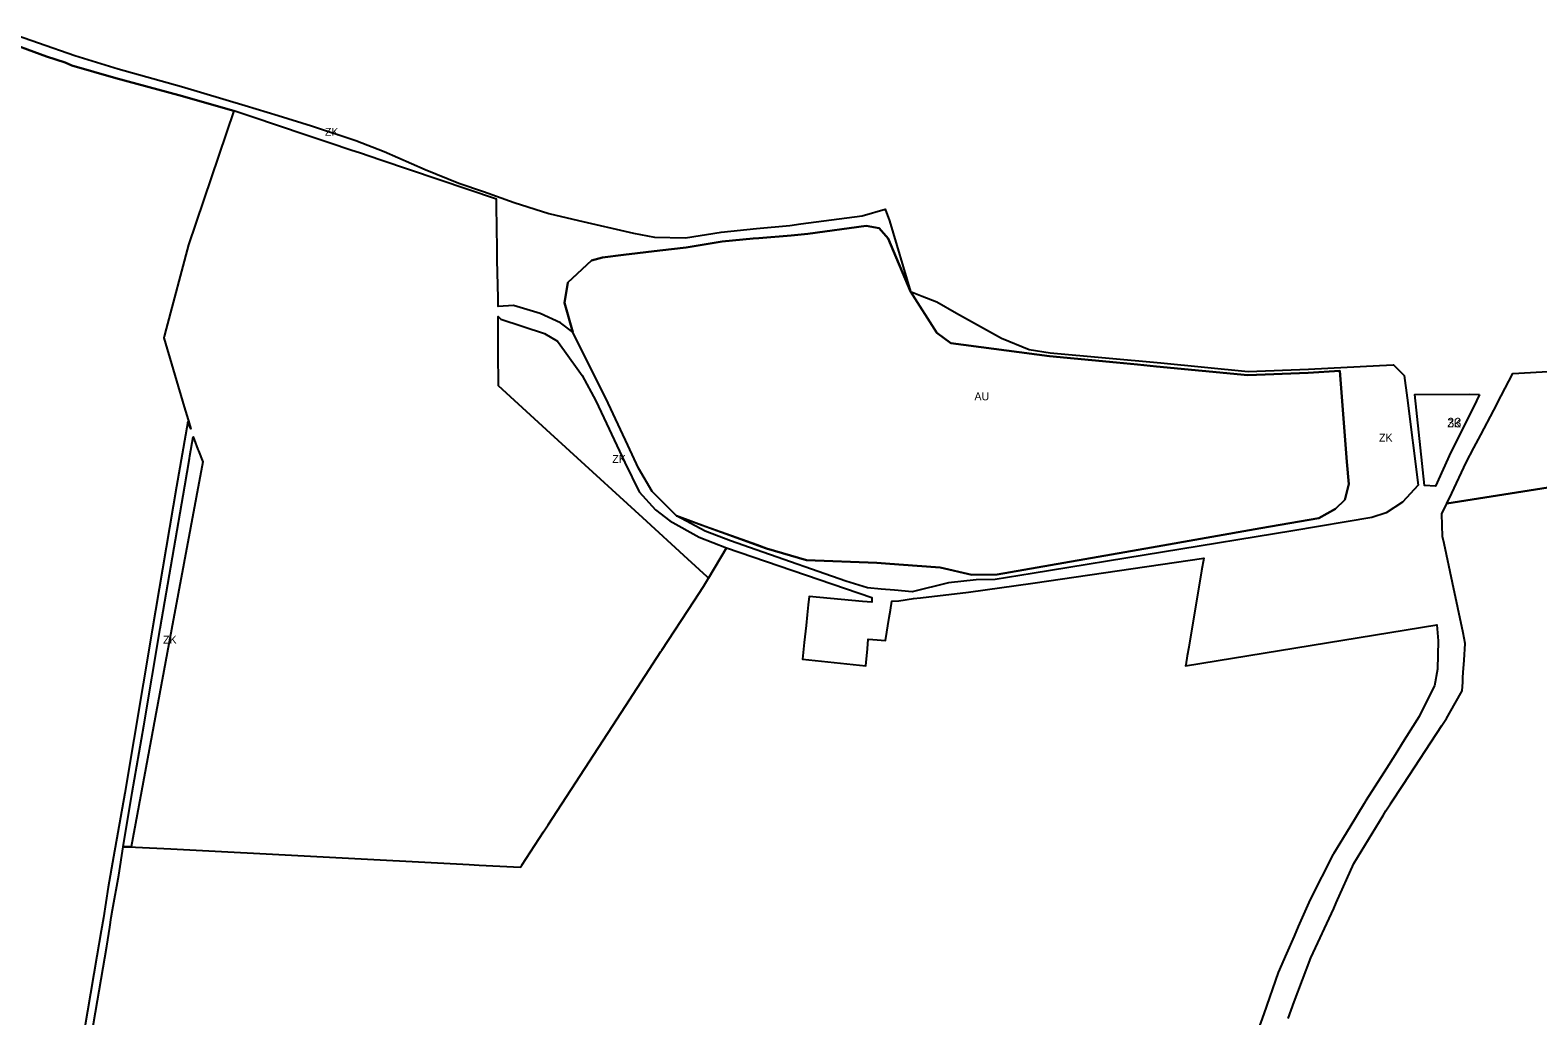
# Model space of a CAD drawing. Extents: x -541351 to -537540, y -1162694 to -1159725.
# Drawn here: x -540409 to -539459, y -1160407 to -1159785 of the extents above; entities that cross this region are included whole.
import ezdxf

# ---------------------------------------------------------------- set-up
doc = ezdxf.new("R2010")
doc.units = 0
for name, color, linetype in [('90710013', 7, 'Continuous'), ('90710023', 7, 'Continuous'), ('90730023', 7, 'Continuous'), ('90750013', 7, 'Continuous'), ('ID_navrh', 7, 'Continuous')]:
    doc.layers.add(name, color=color, linetype=linetype)

msp = doc.modelspace()

# ---------------------------------------------------------------- linework, layer by layer
at = {"layer": '90710013'}
msp.add_lwpolyline([(-540426.9, -1159785.09), (-540381.17, -1159801.03), (-540353.86, -1159809.47), (-540313.98, -1159820.68), (-540273.9, -1159832.58), (-540253.02, -1159838.81), (-540231.99, -1159845.43), (-540204.14, -1159854.61), (-540186.16, -1159861.7), (-540160.34, -1159872.99), (-540139.14, -1159881.68), (-540123.57, -1159886.83), (-540104.23, -1159893.79), (-540082.45, -1159900.78), (-540063.64, -1159905.2), (-540028.95, -1159913.17), (-540015.69, -1159915.65), (-539996.27, -1159916.14), (-539973.83, -1159912.54), (-539951.52, -1159910.12), (-539930.48, -1159908.19), (-539923.64, -1159907.28), (-539884.96, -1159902.13), (-539884.96, -1159902.13), (-539870.3, -1159897.92), (-539867.6, -1159905.3), (-539854.42, -1159949.89), (-539854.468, -1159949.886), (-539868.5, -1159916.51), (-539874.18, -1159909.94), (-539882.33, -1159908.49), (-539882.33, -1159908.49), (-539919.19, -1159913.5), (-539929.66, -1159914.61), (-539950.01, -1159916.19), (-539953.64, -1159916.52), (-539973.07, -1159918.29), (-539992.07, -1159921.5), (-539995.75, -1159922.12), (-539995.75, -1159922.12), (-540012.42, -1159924.12), (-540035.405, -1159926.701), (-540048.61, -1159928.47), (-540055.54, -1159930.37), (-540070.308, -1159944.24), (-540072.499, -1159957.081), (-540067.3, -1159975.45), (-540067.3, -1159975.45), (-540074.99, -1159969.67), (-540087.85, -1159963.71), (-540104.63, -1159958.67), (-540114.34, -1159959.41), (-540114.368, -1159953.951), (-540114.86, -1159930.13), (-540114.86, -1159930.13), (-540115, -1159923.02), (-540115.3, -1159896.16), (-540115.35, -1159891.67), (-540188.28, -1159867.11), (-540201.81, -1159862.55), (-540206.56, -1159860.95), (-540220.81, -1159856.16), (-540234.15, -1159851.66), (-540254.76, -1159844.72), (-540267.64, -1159840.39), (-540281.01, -1159835.88), (-540315.69, -1159826.05), (-540355.38, -1159815.32), (-540383.07, -1159807.44), (-540387.33, -1159805.56), (-540399.07, -1159801.69), (-540428.8, -1159790.68)], dxfattribs=at)
for points in [[(-539550.023, -1159996.124), (-539550.023, -1159996.124), (-539548.59, -1159997.61), (-539548.59, -1159997.61), (-539543.22, -1160002.75), (-539541.38, -1160016.88), (-539534.463, -1160072.073), (-539544.32, -1160082.78), (-539554.63, -1160089.47), (-539563.53, -1160092.42), (-539613.52, -1160100.78), (-539777.83, -1160127.75), (-539801.1, -1160131.48), (-539813.107, -1160131.779), (-539830.37, -1160133.62), (-539853.3, -1160139.26), (-539864.5, -1160138.25), (-539872.87, -1160137.5), (-539881.45, -1160136.75), (-539895.17, -1160132.58), (-539951.75, -1160112.76), (-539967.97, -1160107.08), (-539983.78, -1160100.94), (-540001.97, -1160091.42), (-539945.251, -1160111.88), (-539919.896, -1160119.24), (-539875.719, -1160120.923), (-539870.143, -1160121.338), (-539870.143, -1160121.338), (-539861.745, -1160121.961), (-539835.651, -1160123.899), (-539815.751, -1160128.53), (-539799.825, -1160128.268), (-539702.516, -1160111.209), (-539633.633, -1160099.134), (-539597.008, -1160092.713), (-539586.514, -1160086.893), (-539580.553, -1160081.292), (-539578.19, -1160071.326), (-539579.301, -1160057.333), (-539583.865, -1159999.82), (-539583.865, -1159999.82), (-539603.82, -1160001.07), (-539641.86, -1160002.73), (-539699.4, -1159997.18), (-539711.31, -1159995.96), (-539724.64, -1159994.55), (-539766.75, -1159990.7), (-539828.919, -1159982.485), (-539837.787, -1159976.019), (-539854.42, -1159949.89), (-539847.07, -1159952.76), (-539837.92, -1159956.31), (-539825.4, -1159963.61), (-539796.96, -1159979.23), (-539779.53, -1159986.52), (-539766.36, -1159988.66), (-539696.71, -1159994.91), (-539641.55, -1160000.23), (-539603.54, -1159998.8), (-539558.79, -1159996.56)], [(-539970.46, -1160111.61), (-539981.66, -1160130.71), (-539982.55, -1160129.89), (-539994.82, -1160118.65), (-540023.21, -1160092.63), (-540023.21, -1160092.63), (-540032.85, -1160083.79), (-540032.85, -1160083.79), (-540059.54, -1160059.34), (-540081.35, -1160039.35), (-540114.15, -1160009.28), (-540114.23, -1159988.02), (-540114.32, -1159965.74), (-540114.32, -1159965.74), (-540112.66, -1159967.27), (-540085.04, -1159976.32), (-540076.91, -1159981.29), (-540072.59, -1159987.34), (-540061.44, -1160002.94), (-540052.86, -1160018.84), (-540034.45, -1160057.61), (-540025.38, -1160076.27), (-540015.06, -1160087.48), (-540006.2, -1160094.54), (-540006.2, -1160094.54), (-539987.61, -1160104.72)], [(-540305.99, -1160043.28), (-540303.55, -1160049.43), (-540303.16, -1160050.41), (-540300.46, -1160057.21), (-540320.13, -1160162.91), (-540331.53, -1160224.16), (-540345.66, -1160300.06), (-540350.6, -1160299.99), (-540345.01, -1160265.76), (-540337.62, -1160223.7), (-540327.33, -1160162.37), (-540311.8, -1160072.45), (-540308.83, -1160055.13), (-540308.57, -1160053.59), (-540306.51, -1160041.57)]]:
    msp.add_lwpolyline(points, close=True, dxfattribs=at)
at = {"layer": '90710023'}
msp.add_lwpolyline([(-539495.67, -1160014.74), (-539497.71, -1160018.84), (-539510.76, -1160045.13), (-539513.78, -1160051.22), (-539523.43, -1160072.73), (-539530.43, -1160072.14), (-539536.54, -1160014.93), (-539502.2, -1160014.56)], close=True, dxfattribs=at)
at = {"layer": '90730023'}
msp.add_lwpolyline([(-539504.15, -1160057.74), (-539499.27, -1160048.44), (-539494.95, -1160040.2), (-539486.82, -1160024.7), (-539482.04, -1160015.57), (-539474.65, -1160001.49), (-539441.58, -1159999.6), (-539426.66, -1159997.49), (-539378.27, -1159985.56), (-539357.29, -1159979.97), (-539338.63, -1159973.85), (-539312.29, -1159964.05), (-539277.38, -1159950.13), (-539253.79, -1159939.77), (-539256.52, -1159952.89), (-539261.76, -1159978), (-539266.2, -1159999.29), (-539267.32, -1160019.26), (-539320.05, -1160041.46), (-539357.51, -1160053.36), (-539416.53, -1160067.73), (-539516.34, -1160083.61), (-539513.23, -1160077.01)], close=True, dxfattribs=at)
at = {"layer": '90750013'}
for points in [[(-540428.8, -1159790.68), (-540399.07, -1159801.69), (-540387.33, -1159805.56), (-540383.07, -1159807.44), (-540355.38, -1159815.32), (-540315.69, -1159826.05), (-540281.01, -1159835.88), (-540309.48, -1159920.55), (-540323.53, -1159973.38), (-540324.82, -1159978.24), (-540325.05, -1159979.1), (-540312.2, -1160022.66), (-540309.79, -1160030.84), (-540309.61, -1160031.46), (-540308.05, -1160036.54), (-540310.02, -1160032.13), (-540317.01, -1160072.74), (-540332.5, -1160163.53), (-540349.68, -1160266.25), (-540356.83, -1160306.42), (-540360.1, -1160325.54), (-540363.17, -1160344.9), (-540364.58, -1160352.98), (-540367.38, -1160369.03), (-540379.07, -1160438.35)], [(-539616.32, -1160408.3), (-539612.5, -1160397.88), (-539602.14, -1160370.05), (-539587.64, -1160338.97), (-539586.08, -1160335.4), (-539574.91, -1160310.55), (-539556.49, -1160280.21), (-539554.76, -1160277.35), (-539551.86, -1160272.91), (-539543.76, -1160260.52), (-539519.57, -1160223.53), (-539516.64, -1160219.04), (-539511.16, -1160209.5), (-539506.72, -1160201.77), (-539506.35, -1160196.13), (-539506.17, -1160193.22), (-539505.96, -1160190.04), (-539505.45, -1160182.31), (-539504.78, -1160171.93), (-539506.16, -1160165.16), (-539512.88, -1160133.53), (-539518.09, -1160108.82), (-539519.03, -1160104.35), (-539519.41, -1160090.12), (-539516.34, -1160083.61), (-539416.53, -1160067.73)], [(-540371.68, -1160425.08), (-540361.01, -1160362.65), (-540359.02, -1160350.72), (-540358.21, -1160344.57), (-540357.49, -1160339.82), (-540353.51, -1160317.83), (-540350.6, -1160299.99), (-540345.66, -1160300.06), (-540342.83, -1160300.35), (-540320.73, -1160301.36), (-540132.7, -1160311.22), (-540126.4, -1160311.55), (-540100.25, -1160312.92), (-540099.35, -1160311.53), (-540085.75, -1160290.64), (-540082.84, -1160286.17), (-540036.63, -1160215.17), (-540011.71, -1160176.88), (-540011.18, -1160176.06), (-539990.85, -1160144.83), (-539985, -1160135.84), (-539981.66, -1160130.71), (-539970.46, -1160111.61), (-539970.46, -1160111.61), (-539878.88, -1160142.86), (-539878.77, -1160145.8), (-539884.65, -1160145.26), (-539918.38, -1160142.14), (-539918.92, -1160147.4), (-539919.56, -1160153.7), (-539920.25, -1160160.44), (-539921.36, -1160171.22), (-539922.43, -1160181.71), (-539882.63, -1160185.93), (-539881.59, -1160175.1), (-539881.015, -1160169.128), (-539878.185, -1160169.34), (-539870.249, -1160169.921), (-539870.249, -1160169.921), (-539867.81, -1160155.49), (-539867.03, -1160150.82), (-539866.21, -1160145.17), (-539861.77, -1160144.89), (-539852.54, -1160143.49), (-539848.219, -1160143.04), (-539817.86, -1160139.54), (-539777.21, -1160133.77), (-539669.5, -1160118.03), (-539670.89, -1160125.91), (-539678.95, -1160174.24), (-539679.95, -1160179.6), (-539680.94, -1160185.37), (-539681.12, -1160185.89), (-539522.63, -1160160.16), (-539521.72, -1160170.16), (-539522.29, -1160187.99), (-539524.21, -1160198.49), (-539528.99, -1160208.07), (-539533.82, -1160217.78), (-539543.16, -1160232.76), (-539548.99, -1160242.09), (-539555.83, -1160252.97), (-539567.65, -1160271.23), (-539568.53, -1160272.74), (-539577.57, -1160287.59), (-539587.82, -1160304.43), (-539587.98, -1160304.74), (-539602.6, -1160333.33), (-539609.97, -1160350.24), (-539612.64, -1160356.38), (-539617.44, -1160367.38), (-539622.59, -1160379.21), (-539631.8, -1160405.4), (-539638.38, -1160424.12)]]:
    msp.add_lwpolyline(points, dxfattribs=at)
msp.add_lwpolyline([(-539882.33, -1159908.49), (-539882.33, -1159908.49), (-539874.18, -1159909.94), (-539868.5, -1159916.51), (-539854.468, -1159949.886), (-539854.42, -1159949.89), (-539837.787, -1159976.019), (-539828.919, -1159982.485), (-539766.75, -1159990.7), (-539724.64, -1159994.55), (-539711.31, -1159995.96), (-539699.4, -1159997.18), (-539641.86, -1160002.73), (-539603.82, -1160001.07), (-539583.865, -1159999.82), (-539579.301, -1160057.333), (-539578.19, -1160071.326), (-539580.553, -1160081.292), (-539586.514, -1160086.893), (-539597.008, -1160092.713), (-539633.633, -1160099.134), (-539702.516, -1160111.209), (-539799.825, -1160128.268), (-539815.751, -1160128.53), (-539835.651, -1160123.899), (-539861.745, -1160121.961), (-539870.143, -1160121.338), (-539870.143, -1160121.338), (-539875.719, -1160120.923), (-539919.896, -1160119.24), (-539945.251, -1160111.88), (-539951.254, -1160109.715), (-539951.254, -1160109.715), (-539983.749, -1160097.993), (-539983.749, -1160097.993), (-540001.97, -1160091.42), (-540017.28, -1160076.06), (-540025.88, -1160061.24), (-540032.65, -1160046.74), (-540046.5, -1160017.09), (-540051.03, -1160008.01), (-540067.3, -1159975.45), (-540072.499, -1159957.081), (-540070.308, -1159944.24), (-540055.54, -1159930.37), (-540048.61, -1159928.47), (-540035.405, -1159926.701), (-540012.42, -1159924.12), (-539995.75, -1159922.12), (-539992.07, -1159921.5), (-539973.07, -1159918.29), (-539953.64, -1159916.52), (-539950.01, -1159916.19), (-539929.66, -1159914.61), (-539919.19, -1159913.5)], close=True, dxfattribs=at)

# ---------------------------------------------------------------- texts
at = {"layer": '90710013'}
for rotation, p in [(360, (-540223.515, -1159851.695)), (360, (-539559.111, -1160044.575)), (0, (-540042.39, -1160057.97)), (360, (-540325.53, -1160171.936))]:
    msp.add_text('ZK', height=5, rotation=rotation, dxfattribs=at).set_placement(p)
at = {"layer": '90710023'}
msp.add_text('ZK', height=5, rotation=0, dxfattribs=at).set_placement((-539516.105, -1160035.556))
at = {"layer": '90750013'}
msp.add_text('AU', height=5, rotation=360, dxfattribs=at).set_placement((-539814.109, -1160018.51))
at = {"layer": 'ID_navrh'}
msp.add_text('33', height=6, rotation=0, dxfattribs=at).set_placement((-539516.105, -1160035.556))

doc.saveas('drawing.dxf')
